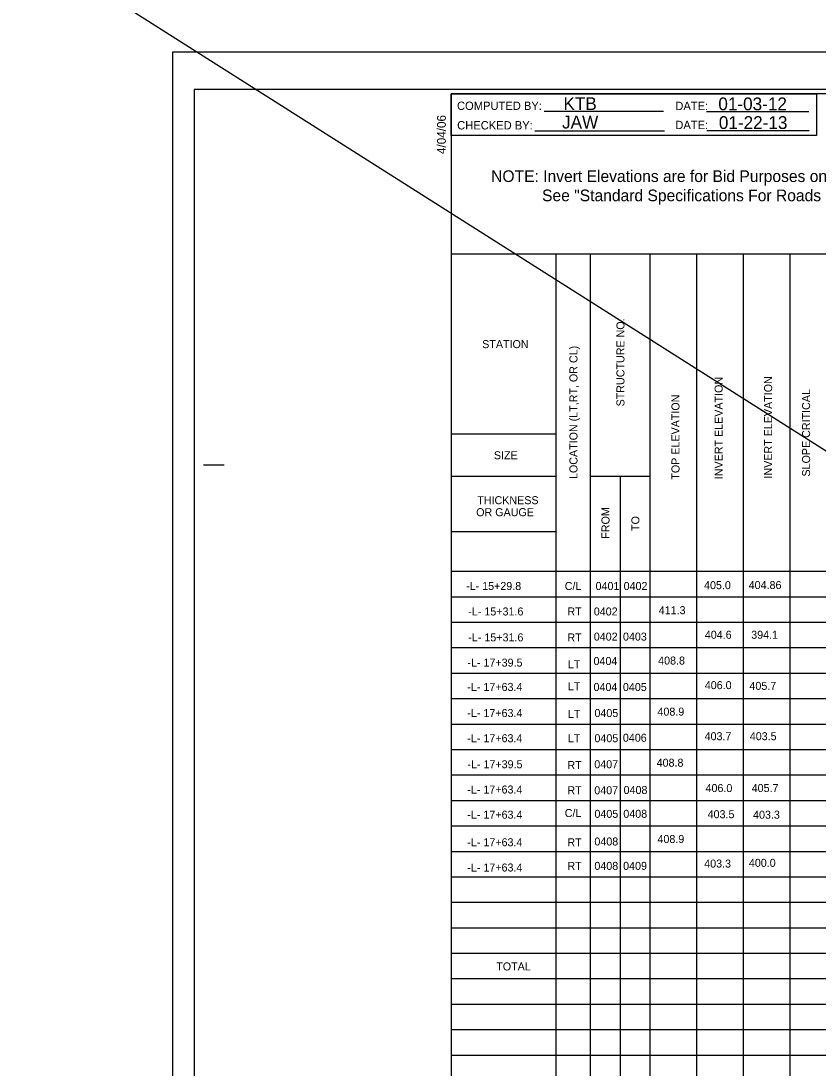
# Model space of a CAD drawing. Extents: x 573359 to 575895, y -54193 to -50493.
# Drawn here: x 573528 to 574005, y -52448 to -51820 of the extents above; entities that cross this region are included whole.
import ezdxf

# ---------------------------------------------------------------- set-up
doc = ezdxf.new("R2010")
doc.units = 0
for name, color, linetype in [('Prop Dimension Text', 7, 'Continuous'), ('Sheet Cutting Line CELL', 7, 'Continuous'), ('Sheet Pipe Summary CELL', 7, 'Continuous'), ('Sheet Pipe Summary Grid CELL', 7, 'Continuous'), ('Sheet Plot Border Inside CELL', 7, 'Continuous'), ('Sheet Plot Border Outside CELL', 7, 'Continuous')]:
    doc.layers.add(name, color=color, linetype=linetype)

msp = doc.modelspace()

# ---------------------------------------------------------------- linework, layer by layer
at = {"layer": 'Prop Dimension Text'}
msp.add_line((573527.78, -51771.9), (575540.59, -53049.47), dxfattribs=at)
at = {"layer": 'Sheet Cutting Line CELL'}
for p, q in [((575302.66, -51839.08), (573618.66, -51839.08)), ((573618.66, -51839.08), (573618.66, -52939.08))]:
    msp.add_line(p, q, dxfattribs=at)
at = {"layer": 'Sheet Pipe Summary CELL'}
for p, q in [((573841.31, -51874.48), (573912.86, -51874.48)), ((573938.66, -51874.63), (574000.06, -51874.63)), ((573835.86, -51886.18), (573913.56, -51886.18)), ((573938.81, -51886.13), (574000.21, -51886.13)), ((573637.16, -52086.58), (573649.66, -52086.58)), ((573637.16, -52086.58), (573649.66, -52086.58))]:
    msp.add_line(p, q, dxfattribs=at)
for points in [[(575285.66, -51864.08), (573785.66, -51864.08), (573785.66, -52914.08), (575285.66, -52914.08)], [(573785.66, -51864.08), (574004.66, -51864.08), (574004.66, -51889.08), (573785.66, -51889.08)]]:
    msp.add_lwpolyline(points, close=True, dxfattribs=at)
at = {"layer": 'Sheet Pipe Summary Grid CELL'}
for p, q in [((575285.66, -51960.18), (573785.66, -51960.28)), ((573848.66, -52914.08), (573848.61, -51960.28)), ((573869.21, -52914.08), (573869.16, -51960.28)), ((573904.96, -52914.08), (573904.91, -51960.28)), ((573932.93, -52914.07), (573932.88, -51960.27)), ((573960.91, -52914.07), (573960.86, -51960.27)), ((573988.88, -52914.07), (573988.83, -51960.27)), ((573848.61, -52068.13), (573785.66, -52068.13)), ((573848.61, -52093.53), (573785.66, -52093.53)), ((573904.92, -52093.53), (573869.17, -52093.53)), ((573887.11, -52914.08), (573887.06, -52093.53)), ((573848.61, -52126.68), (573785.66, -52126.68)), ((575285.66, -52150.58), (573785.66, -52150.58)), ((575285.66, -52165.88), (573785.66, -52165.88)), ((575285.66, -52181.13), (573785.66, -52181.13)), ((575285.66, -52196.38), (573785.66, -52196.38)), ((575285.66, -52211.68), (573785.66, -52211.68)), ((575285.66, -52226.93), (573785.66, -52226.93)), ((575285.66, -52242.23), (573785.66, -52242.23)), ((575285.66, -52257.48), (573785.66, -52257.48)), ((575285.66, -52272.73), (573785.66, -52272.73)), ((575285.66, -52288.03), (573785.66, -52288.03)), ((575285.66, -52303.28), (573785.66, -52303.28)), ((575285.66, -52318.58), (573785.66, -52318.58)), ((575285.66, -52333.83), (573785.66, -52333.83)), ((575285.66, -52349.08), (573785.66, -52349.08)), ((575285.66, -52364.38), (573785.66, -52364.38)), ((575285.66, -52379.63), (573785.66, -52379.63)), ((575285.66, -52394.93), (573785.66, -52394.93)), ((575285.66, -52410.18), (573785.66, -52410.18)), ((575285.66, -52425.43), (573785.66, -52425.43)), ((575285.66, -52440.73), (573785.66, -52440.73))]:
    msp.add_line(p, q, dxfattribs=at)
at = {"layer": 'Sheet Plot Border Inside CELL'}
msp.add_lwpolyline([(573631.66, -52916.63), (575298.16, -52916.63), (575298.16, -51861.53), (573631.66, -51861.53)], close=True, dxfattribs=at)
at = {"layer": 'Sheet Plot Border Outside CELL'}
msp.add_lwpolyline([(573618.66, -52939.08), (575302.66, -52939.08), (575302.66, -51839.08), (573618.66, -51839.08)], close=True, dxfattribs=at)

# ---------------------------------------------------------------- texts
at = {"layer": 'Prop Dimension Text'}
for s, height, p in [('KTB', 7.68, (573852.9, -51873.78)), ('01-03-12', 7.68, (573945.74, -51873.93)), ('JAW', 7.68, (573852.1, -51884.87)), ('01-22-13', 7.68, (573946.04, -51885.15)), ('-L- 15+29.8', 4.8, (573794.57, -52161.65)), ('C/L', 4.8, (573853.67, -52161.65)), ('0401', 4.8, (573872.17, -52161.65)), ('0402', 4.8, (573888.97, -52161.65)), ('405.0', 4.8, (573937.18, -52161.14)), ('404.86', 4.8, (573963.94, -52161.06)), ('-L- 15+31.6', 4.8, (573795.9, -52176.91)), ('RT', 4.8, (573855.29, -52176.91)), ('0402', 4.8, (573871.1, -52176.91)), ('411.3', 4.8, (573910.02, -52176.15)), ('404.6', 4.8, (573937.64, -52190.89)), ('394.1', 4.8, (573965.44, -52190.89)), ('-L- 15+31.6', 4.8, (573795.9, -52192.44)), ('RT', 4.8, (573855.29, -52192.48)), ('0402', 4.8, (573871.1, -52191.99)), ('0403', 4.8, (573888.59, -52191.99)), ('-L- 17+39.5', 4.8, (573795.35, -52207.59)), ('LT', 4.8, (573855.58, -52208.57)), ('0404', 4.8, (573870.94, -52206.62)), ('408.8', 4.8, (573909.66, -52206.35)), ('-L- 17+63.4', 4.8, (573795.31, -52222.18)), ('LT', 4.8, (573855.58, -52221.73)), ('0404', 4.8, (573870.94, -52222.22)), ('0405', 4.8, (573888.56, -52222.22)), ('406.0', 4.8, (573937.62, -52221.09)), ('405.7', 4.8, (573964.38, -52221.53)), ('-L- 17+63.4', 4.8, (573795.31, -52237.83)), ('LT', 4.8, (573855.58, -52238.31)), ('0405', 4.8, (573871.49, -52237.83)), ('408.9', 4.8, (573909.25, -52236.99)), ('-L- 17+63.4', 4.8, (573795.31, -52252.94)), ('LT', 4.8, (573855.58, -52252.94)), ('0405', 4.8, (573871.49, -52252.94)), ('0406', 4.8, (573888.53, -52252.64)), ('403.7', 4.8, (573937.51, -52251.73)), ('403.5', 4.8, (573964.59, -52251.73)), ('-L- 17+39.5', 4.8, (573795.35, -52268.55)), ('RT', 4.8, (573855.29, -52269.03)), ('0407', 4.8, (573871.4, -52268.55)), ('408.8', 4.8, (573908.77, -52267.63)), ('-L- 17+63.4', 4.8, (573795.31, -52283.7)), ('RT', 4.8, (573855.29, -52284.15)), ('0407', 4.8, (573871.4, -52284.15)), ('0408', 4.8, (573888.96, -52283.97)), ('406.0', 4.8, (573938.07, -52282.82)), ('405.7', 4.8, (573965.72, -52282.82)), ('C/L', 4.8, (573853.67, -52297.81)), ('0408', 4.8, (573888.79, -52298.26)), ('-L- 17+63.4', 4.8, (573795.31, -52298.78)), ('0405', 4.8, (573871.49, -52298.29)), ('403.5', 4.8, (573939.32, -52298.52)), ('403.3', 4.8, (573966.56, -52298.8)), ('-L- 17+63.4', 4.8, (573795.31, -52315.32)), ('RT', 4.8, (573855.29, -52315.36)), ('0408', 4.8, (573871.46, -52314.87)), ('408.9', 4.8, (573909.25, -52313.37)), ('RT', 4.8, (573855.29, -52329.5)), ('0408', 4.8, (573871.46, -52329.5)), ('0409', 4.8, (573888.69, -52329.49)), ('403.3', 4.8, (573937.28, -52328.11)), ('400.0', 4.8, (573964.05, -52327.67)), ('-L- 17+63.4', 4.8, (573795.31, -52330.48)), ('TOTAL', 4.8, (573812.65, -52389.81))]:
    msp.add_text(s, height=height, dxfattribs=at).set_placement(p)
at = {"layer": 'Sheet Pipe Summary CELL'}
for s, height, p in [('COMPUTED BY:', 4.9998, (573789.11, -51873.73)), ('DATE:', 5, (573919.96, -51873.83)), ('CHECKED BY:', 4.9998, (573789.21, -51885.43)), ('DATE:', 5, (573919.96, -51885.23)), ('NOTE: Invert Elevations are for Bid Purposes only and shall not be used for project construction stakeout.', 7, (573809.57, -51916.95)), ('See "Standard Specifications For Roads and Structures, Section 300-5".', 7, (573840.1, -51928.48)), ('SIZE', 4.8, (573811.21, -52083.23)), ('THICKNESS', 4.8, (573801.26, -52110.18)), ('OR GAUGE', 4.8, (573800.61, -52117.38))]:
    msp.add_text(s, height=height, dxfattribs=at).set_placement(p)
for s, height, rotation, p in [('4/04/06', 5.25, 90, (573782.41, -51900.19)), ('STRUCTURE NO.', 4.8, 90, (573889.46, -52051.53)), ('STATION', 4.8, 360, (573804.21, -52016.58)), ('LOCATION (LT,RT, OR CL)', 4.8, 90, (573861.31, -52095.08)), ('INVERT ELEVATION', 4.8, 90, (573948.32, -52095.18)), ('INVERT ELEVATION', 4.8, 90, (573977.98, -52094.78)), ('SLOPE CRITICAL', 4.8, 90, (574000.73, -52093.58)), ('TOP ELEVATION', 4.8, 90, (573922.46, -52095.45)), ('FROM', 4.8, 90, (573880.51, -52130.88)), ('TO', 4.8, 90, (573898.41, -52126.23))]:
    msp.add_text(s, height=height, rotation=rotation, dxfattribs=at).set_placement(p)

doc.saveas('drawing.dxf')
